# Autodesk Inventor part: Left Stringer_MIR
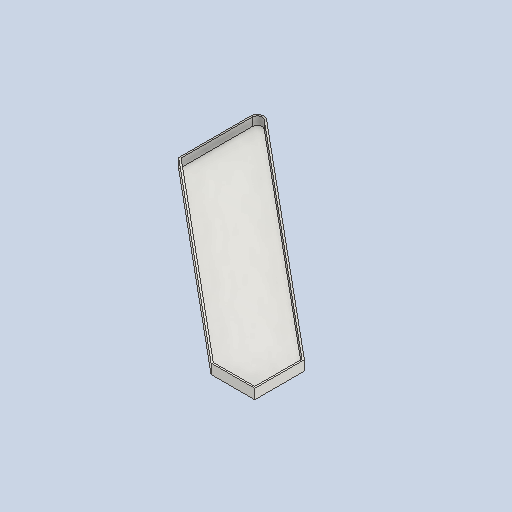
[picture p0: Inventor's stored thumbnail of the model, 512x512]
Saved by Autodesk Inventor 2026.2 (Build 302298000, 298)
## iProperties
Created: 2022-06
Part Number: Left Stringer_MIR
Material: Steel, Galvanized
Document SubType Name: Modeling
Designer: reaumed
Mass: 28099.6 g
Surface Area: 11501.7 cm^2
Volume: 3579.57 cm^3
Density: 7.85 g/cm^3
Appearance: Galvanized
Author: reaumed
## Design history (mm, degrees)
derived "Stringer.ipt"
  sketch "Stringer Profile Sketch"
    geometry: L1 (0, 0)-(914.4, 0) reference; L2 (914.4, 0)-(914.4, -762) reference; L3 (914.4, -762)-(0, -762) reference; L4 (0, -762)-(0, 0) reference; L5 (845.482, -1035.202)-(-68.918, -273.202) reference; L6 (-68.918, -273.202)-(93.689, -78.074) reference; L7 (93.689, -78.074)-(1008.089, -840.074) reference; L8 (1008.089, -840.074)-(845.482, -1035.202) reference; L9 (0, -190.5)-(228.6, -190.5) reference; L10 (0, -190.5)-(0, -330.634) reference; L11 (746.239, -952.5)-(914.4, -952.5) reference; L12 (914.4, -952.5)-(914.4, -762) reference; L13 (0, -1935.112)-(0, 322.519) reference; L14 (2103.33, 0)-(-428.779, 0) reference; L15 (0, -190.5)-(0, -54.23) reference; L16 (93.689, -78.074)-(41.661, -34.717) reference; A1 r 25.4 centre (25.4, -54.23) between (41.661, -34.717) and (0, -54.23) reference; 2 further points
  node "Half the Width Workplane"
feature "Solid2::Stringer.ipt"
tag "TaggingFeature1"
body "Solid2"
